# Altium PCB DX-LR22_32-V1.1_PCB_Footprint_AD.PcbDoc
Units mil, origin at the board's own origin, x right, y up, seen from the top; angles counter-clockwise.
Board outline 6000 x 4000 mil, 2 copper layers (Top, Bottom), stack 12.7 mil thick; 1 components, 0 nets, 10 pads, 0 vias.
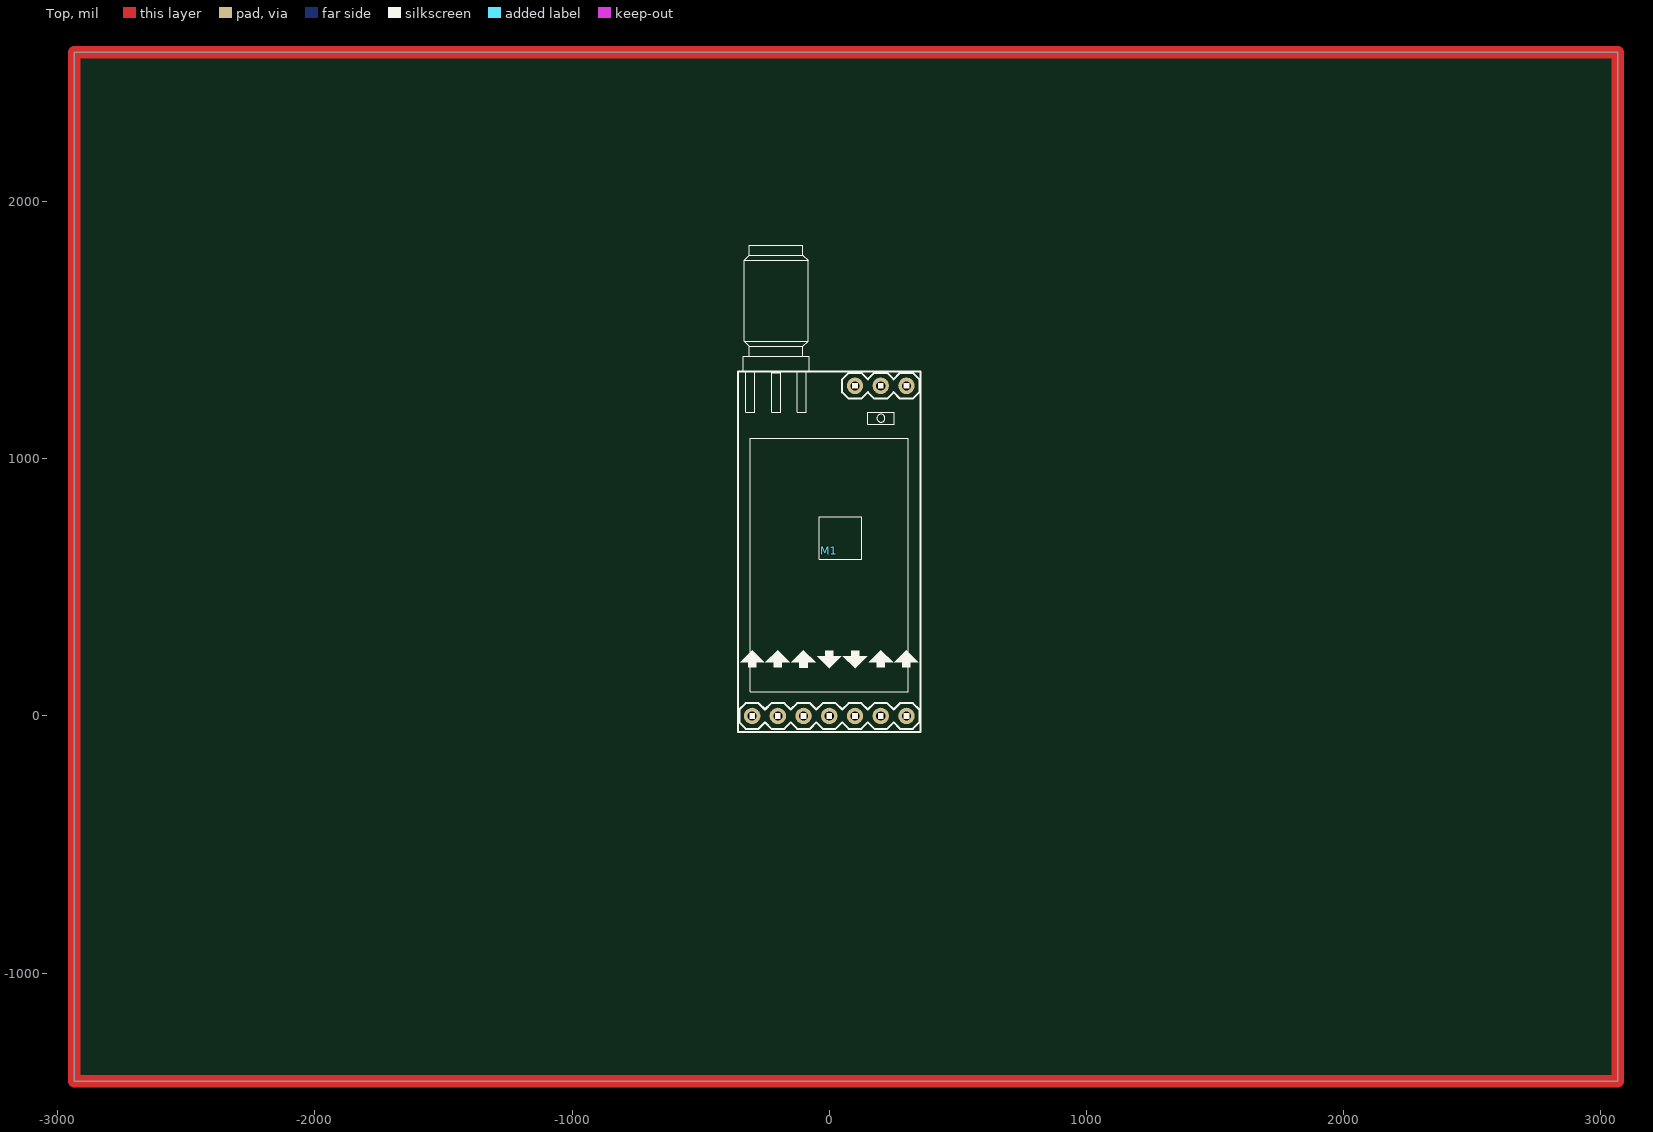
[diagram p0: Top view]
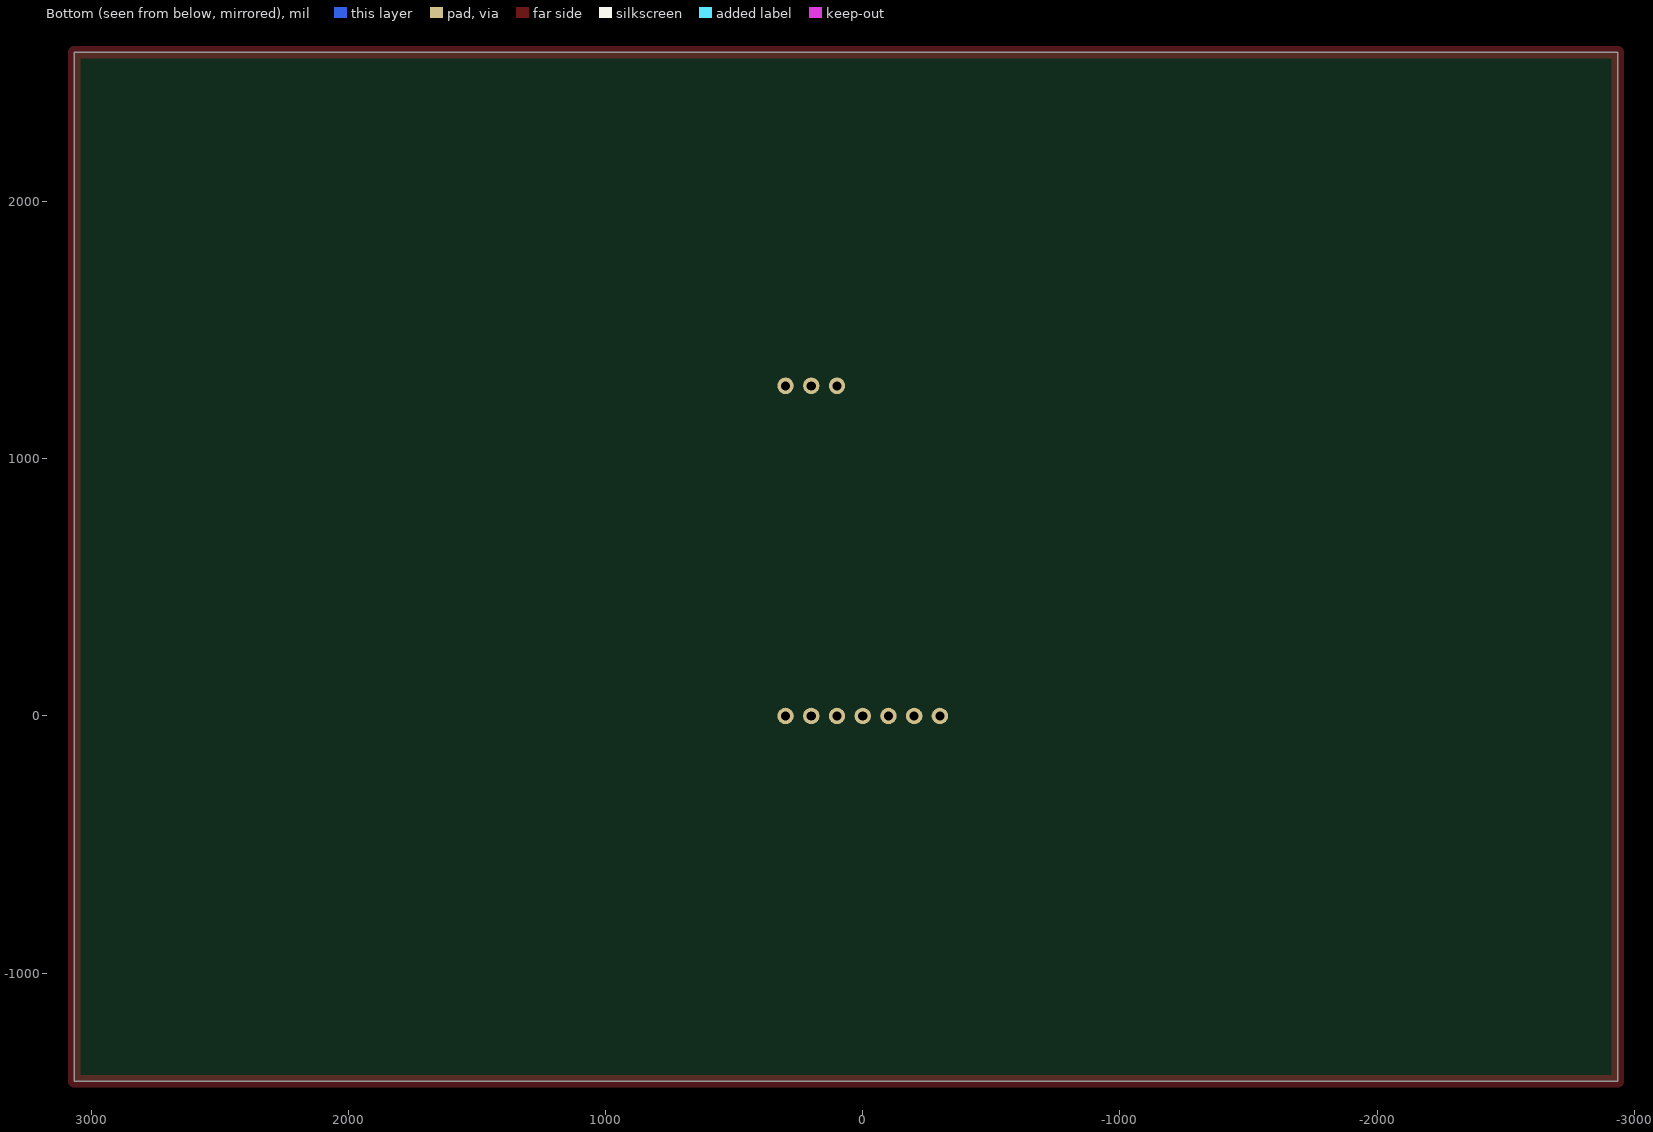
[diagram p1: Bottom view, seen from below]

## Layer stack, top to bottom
Solder Mask Top: solder mask 0.4, Solder Resist, Dk 3.5
Top: signal copper 1.35
Dielectric 1: dielectric 10, FR-4, Dk 4.3
Bottom: signal copper 1.35
Solder Mask Bottom: solder mask 0.4, Solder Resist, Dk 3.5

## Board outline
-2935,-1420 3065,-1420 3065,2580 -2935,2580

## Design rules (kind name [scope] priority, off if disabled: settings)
Clearance "Clearance - Default - DEFAULT - Via" [IsVia vs IsVia] p1: gap=6 ignorepadtopadclearanceinfootprint=FALSE
Clearance "Clearance - Default - DEFAULT- SMD" [IsVia vs IsSMTPin] p2: gap=6 ignorepadtopadclearanceinfootprint=FALSE
Clearance "Clearance - Default - DEFAULT - Net" [All] p3: gap=6 ignorepadtopadclearanceinfootprint=FALSE except(10: Arc-Hole Track-Hole SMDPad-Hole THPad-Hole Via-Hole Fill-Hole Poly-Hole Region-Hole Text-Text Text-Hole)
ComponentClearance "ComponentClearance - Default - DEFAULT" [All] p1: gap=6 collisioncheckmode=3 verticalgap=10 showdistances=FALSE
FanoutControl Fanout_SOIC [IsSOIC] p1: bgadir=Out bgaviamode=Centered fanoutstyle=Auto fanoutdirection=Alternating viagrid=1 // Fanout_SOIC (Default Rule)
FanoutControl Fanout_Small [(CompPinCount < 5)] p2: bgadir=Out bgaviamode=Centered fanoutstyle=Auto fanoutdirection=OutThenIn viagrid=1 // Fanout_Small (Default Rule)
FanoutControl Fanout_LCC [IsLCC] p3: bgadir=Out bgaviamode=Centered fanoutstyle=Auto fanoutdirection=Alternating viagrid=1 // Fanout_LCC (Default Rule)
FanoutControl Fanout_BGA [IsBGA] p4: bgadir=Out bgaviamode=Centered fanoutstyle=Auto fanoutdirection=Alternating viagrid=1 // Fanout_BGA (Default Rule)
HoleToHoleClearance "HoleToHoleClearance - Default - DEFAULT" [All] p1: gap=6 allowstackedmicrovias=TRUE
Length "Default Length" [All] p1: maxlimit=50000 minlimit=0
MaxMinImpedance "Default Impedance" [All] p1: minimum=50.00 maximum=150.0
ParallelSegment "Default Parallel Segment Same Layer" [All] p1: limit=1000 gap=200
ParallelSegment "Default Parallel Segment Adjasent" [All] p2: limit=1000 gap=200
PolygonConnect [All] p1: connectstyle=Relief reliefconductorwidth=10 reliefentries=4 polygonreliefangle="90 Angle" airgapwidth=10
RoutingLayers "RoutingLayers - Default - DEFAULT" [All] p1: top layer_v5=TRUE bottom layer_v5=TRUE
RoutingPriority "RoutingPriority - Default - DEFAULT" [All] p1: routingpriority=3
RoutingTopology "Default Routing Topology" [All] p1: topology=Shortest
RoutingVias "RoutingVias - Default - DEFAULT" [All] p1: holewidth=37 width=55 viastyle="Through Hole" minholewidth=37 minwidth=55 maxholewidth=37 maxwidth=55
SMDToCorner "SMDToCorner - Default - DEFAULT" [All] p1: distance=60000
SolderMaskExpansion [All] p1: expansion=4 istentingtop=FALSE
Width "Default Width" [All] p1: maxlimit=12 minlimit=12 preferedwidth=12
21 further rules are at their usual default settings.

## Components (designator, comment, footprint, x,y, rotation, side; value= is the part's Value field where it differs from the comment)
M1 "DX-LR22_32" DX-LR02 0,0 r0 top

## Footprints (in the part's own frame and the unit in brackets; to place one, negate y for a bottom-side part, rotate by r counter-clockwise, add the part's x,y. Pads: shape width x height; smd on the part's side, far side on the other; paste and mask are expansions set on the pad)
DX-LR02 [mil]
  round 64 hole 35.43: 1(-300,0) 2(-200,0) 3(-100,0) 4(0,0) 5(100,0) 6(200,0) 7(300,0) 8(100,1283.46) 9(200,1283.46) 10(300,1283.46)
  silkscreen extent -354,-63 354,1831

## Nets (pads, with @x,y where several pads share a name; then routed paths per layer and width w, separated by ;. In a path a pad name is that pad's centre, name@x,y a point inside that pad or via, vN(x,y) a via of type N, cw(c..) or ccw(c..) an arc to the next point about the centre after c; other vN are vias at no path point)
pads on no net: M1.1 M1.2 M1.3 M1.4 M1.5 M1.6 M1.7 M1.8 M1.9 M1.10
copper on no net: | length 20000
  Top w47.24: -2935,-1420 -2935,2580 3065,2580 3065,-1420 -2935,-1420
